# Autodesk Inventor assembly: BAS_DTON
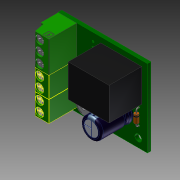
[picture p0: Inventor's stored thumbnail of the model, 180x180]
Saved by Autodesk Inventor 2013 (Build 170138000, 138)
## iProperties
Created: 2021-02
Part Number: BAS_DTON
Document SubType Name: Assembly
Designer: Fede
Author: Fede
Translation Standard: STEP AP214IS
FileName: Open CASCADE Shape Model
PreProcessor: Open CASCADE 6.2
PostProcessor: Build: 138, Release: 2013 RTM - Date: Thu 03/01/2012
Sent Units: millimeter
Uncertainty: 0.0001
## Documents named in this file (17)
- C:\0000 FEDE\16GB\0000 INTERIOR\DE_TMP_BAS\BAS_DTON - demora conexion al energizar\pcb\BOR\turn on\Imported Components\BAS_DTON\BAS_DTON.iam
- C:\0000 FEDE\16GB\0000 INTERIOR\DE_TMP_BAS\BAS_DTON - demora conexion al energizar\pcb\BOR\turn on\Imported Components\BAS_DTON\Board.ipt
- C:\0000 FEDE\16GB\0000 INTERIOR\DE_TMP_BAS\BAS_DTON - demora conexion al energizar\pcb\BOR\turn on\Imported Components\BAS_DTON\R3.iam
- C:\0000 FEDE\16GB\0000 INTERIOR\DE_TMP_BAS\BAS_DTON - demora conexion al energizar\pcb\BOR\turn on\Imported Components\BAS_DTON\JP4.iam
- C:\0000 FEDE\16GB\0000 INTERIOR\DE_TMP_BAS\BAS_DTON - demora conexion al energizar\pcb\BOR\turn on\Imported Components\BAS_DTON\JP3.iam
- C:\0000 FEDE\16GB\0000 INTERIOR\DE_TMP_BAS\BAS_DTON - demora conexion al energizar\pcb\BOR\turn on\Imported Components\BAS_DTON\JP2.iam
- C:\0000 FEDE\16GB\0000 INTERIOR\DE_TMP_BAS\BAS_DTON - demora conexion al energizar\pcb\BOR\turn on\Imported Components\BAS_DTON\R2.iam
- C:\0000 FEDE\16GB\0000 INTERIOR\DE_TMP_BAS\BAS_DTON - demora conexion al energizar\pcb\BOR\turn on\Imported Components\BAS_DTON\R8.iam
- C:\0000 FEDE\16GB\0000 INTERIOR\DE_TMP_BAS\BAS_DTON - demora conexion al energizar\pcb\BOR\turn on\Imported Components\BAS_DTON\D2.iam
- C:\0000 FEDE\16GB\0000 INTERIOR\DE_TMP_BAS\BAS_DTON - demora conexion al energizar\pcb\BOR\turn on\Imported Components\BAS_DTON\R7.iam
- C:\0000 FEDE\16GB\0000 INTERIOR\DE_TMP_BAS\BAS_DTON - demora conexion al energizar\pcb\BOR\turn on\Imported Components\BAS_DTON\Q1.iam
- C:\0000 FEDE\16GB\0000 INTERIOR\DE_TMP_BAS\BAS_DTON - demora conexion al energizar\pcb\BOR\turn on\Imported Components\BAS_DTON\C3.iam
- C:\0000 FEDE\16GB\0000 INTERIOR\DE_TMP_BAS\BAS_DTON - demora conexion al energizar\pcb\BOR\turn on\Imported Components\BAS_DTON\R1.iam
- C:\0000 FEDE\16GB\0000 INTERIOR\DE_TMP_BAS\BAS_DTON - demora conexion al energizar\pcb\BOR\turn on\Imported Components\BAS_DTON\K1.iam
- C:\0000 FEDE\16GB\0000 INTERIOR\DE_TMP_BAS\BAS_DTON - demora conexion al energizar\pcb\BOR\turn on\Imported Components\BAS_DTON\R5.iam
- C:\0000 FEDE\16GB\0000 INTERIOR\DE_TMP_BAS\BAS_DTON - demora conexion al energizar\pcb\BOR\turn on\Imported Components\BAS_DTON\D3.iam
- C:\0000 FEDE\16GB\0000 INTERIOR\DE_TMP_BAS\BAS_DTON - demora conexion al energizar\pcb\BOR\turn on\Imported Components\BAS_DTON\Free-Models.iam
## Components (16 placed, 16 different names)
1. Board:1
2. R3:1 [sub-assembly]
3. JP4:1 [sub-assembly]
4. JP3:1 [sub-assembly]
5. JP2:1 [sub-assembly]
6. R2:1 [sub-assembly]
7. R8:1 [sub-assembly]
8. D2:1 [sub-assembly]
9. R7:1 [sub-assembly]
10. Q1:1 [sub-assembly]
11. C3:1 [sub-assembly]
12. R1:1 [sub-assembly]
13. K1:1 [sub-assembly]
14. R5:1 [sub-assembly]
15. D3:1 [sub-assembly]
16. Free-Models:1 [sub-assembly]
